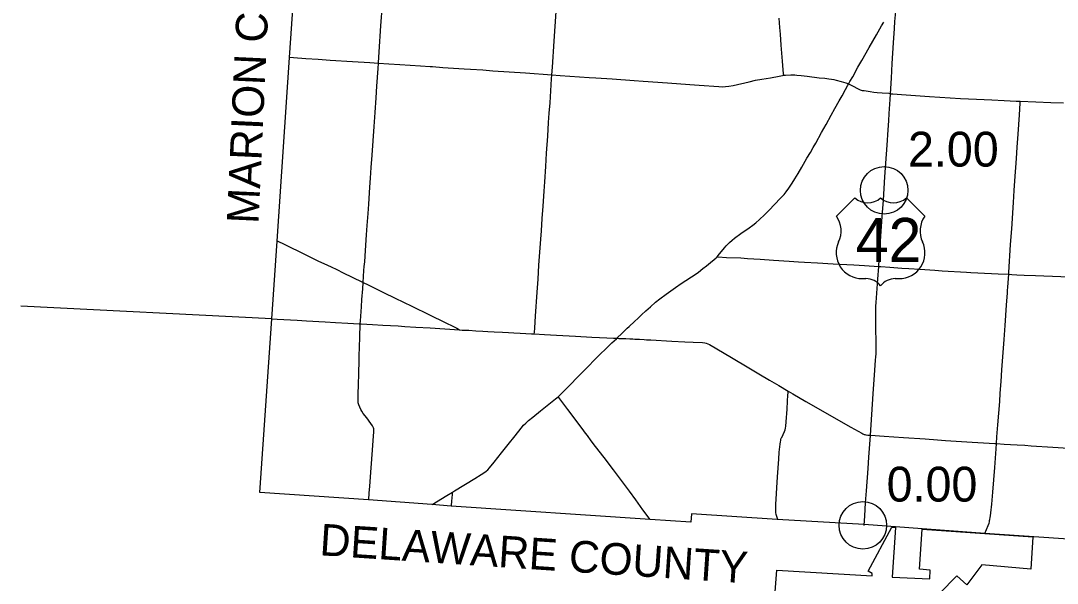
# Model space of a CAD drawing. Extents: x 1815539 to 1947826, y 273303 to 993194.
# Drawn here: x 1815539 to 1848246, y 878565 to 896327 of the extents above; entities that cross this region are included whole.
import ezdxf

# ---------------------------------------------------------------- set-up
doc = ezdxf.new("R2010")
doc.units = 0
for name, color, linetype in [('Default', 7, 'Continuous'), ('GM_X_Adjacent_County_Text', 7, 'Continuous'), ('GM_X_Corporation', 7, 'Continuous'), ('GM_X_County', 7, 'Continuous'), ('GM_X_County_Road', 7, 'Continuous'), ('GM_X_State_Route', 7, 'Continuous'), ('GM_X_Township_Road', 7, 'Continuous'), ('GM_X_US_Route', 7, 'Continuous'), ('PV_X_EOP', 7, 'Continuous'), ('PV_X_Shoulder', 7, 'Continuous')]:
    doc.layers.add(name, color=color, linetype=linetype)

msp = doc.modelspace()

# ---------------------------------------------------------------- linework, layer by layer
at = {"layer": 'Default'}
for centre in [(1842785, 890971), (1842112, 880395)]:
    msp.add_circle(centre, 750, dxfattribs=at)
at = {"layer": 'GM_X_Corporation'}
msp.add_lwpolyline([(1839212, 876522), (1839395, 878979), (1842403, 878797), (1842406, 878874), (1842276, 878944), (1843026, 880333), (1843137, 880326), (1843037, 878758), (1844222, 878701), (1844237, 878976), (1843894, 879006), (1843983, 880269), (1847478, 880034), (1847407, 879013), (1845866, 879149), (1845394, 878513), (1845080, 878796), (1844533, 878238)], dxfattribs=at)
at = {"layer": 'GM_X_County'}
msp.add_lwpolyline([(1850147, 879854), (1845959, 880135), (1842150, 880416), (1839410, 880574), (1836708, 880754), (1836682, 880495), (1835395, 880574), (1829123, 881005), (1828513, 881052), (1826517, 881205), (1823082, 881429), (1823458, 886911), (1823627, 889370), (1824025, 895167), (1824431, 901093)], dxfattribs=at)
at = {"layer": 'GM_X_County_Road'}
for points in [[(1826827, 894987), (1826827, 895001), (1826851, 895345), (1826907, 896163), (1826952, 896835), (1826990, 897375), (1827034, 898063), (1827056, 898390), (1827082, 898783), (1827090, 898914), (1827110, 899258), (1827135, 899684), (1827164, 900142), (1827200, 900716), (1827209, 900922)], [(1841658, 894328), (1841703, 894404), (1841790, 894557), (1841958, 894857), (1842079, 895071), (1842313, 895484), (1842540, 895881), (1842701, 896166), (1842771, 896286)], [(1824029, 895174), (1824145, 895166), (1824536, 895137), (1824929, 895108), (1825305, 895085), (1826010, 895043), (1826550, 895005), (1826827, 894987)], [(1826343, 888063), (1826370, 888438), (1826380, 888568), (1826392, 888715), (1826419, 889075), (1826454, 889567), (1826474, 889861), (1826500, 890238), (1826520, 890532), (1826554, 891073), (1826572, 891351), (1826597, 891695), (1826625, 892087), (1826688, 892988), (1826719, 893430), (1826751, 893888), (1826777, 894264), (1826817, 894821), (1826827, 894987)], [(1826827, 894987), (1827156, 894965), (1827506, 894942)], [(1827506, 894942), (1828155, 894900), (1828455, 894881)], [(1828455, 894881), (1828532, 894877), (1828859, 894855), (1829530, 894810), (1829727, 894798), (1830120, 894771), (1830431, 894749), (1831462, 894677), (1832301, 894618)], [(1832301, 894618), (1832559, 894602), (1833475, 894538), (1833688, 894522), (1834196, 894488), (1834899, 894439), (1835177, 894417), (1835947, 894363), (1836650, 894312), (1836945, 894290), (1837567, 894246), (1837698, 894242), (1837781, 894246), (1837879, 894258), (1838024, 894284), (1838520, 894400), (1838728, 894446), (1838921, 894481), (1839196, 894528), (1839471, 894575), (1839625, 894604), (1839631, 894605)], [(1837518, 888876), (1837551, 888917), (1837744, 889159), (1837799, 889220), (1837903, 889325), (1837988, 889402), (1838065, 889464), (1838264, 889608), (1838521, 889784), (1838642, 889869), (1838731, 889941), (1838854, 890049), (1839010, 890195), (1839158, 890347), (1839507, 890717), (1839630, 890845), (1839695, 890924), (1839778, 891045), (1839879, 891194), (1839966, 891333), (1840066, 891502), (1840183, 891699), (1840348, 891983), (1840455, 892167), (1840546, 892323), (1840627, 892465), (1840809, 892795), (1840954, 893053), (1841113, 893340), (1841232, 893555), (1841367, 893799), (1841454, 893956), (1841565, 894157), (1841635, 894287), (1841658, 894328)], [(1842980, 894022), (1843052, 894018), (1843328, 893998), (1843917, 893956), (1844212, 893937), (1845194, 893876), (1845702, 893848), (1846177, 893824), (1846571, 893808), (1846948, 893791), (1847079, 893786)], [(1847079, 893786), (1847571, 893768), (1848046, 893749), (1848439, 893732)], [(1834737, 886671), (1834904, 886828), (1835023, 886940), (1835130, 887042), (1835261, 887166), (1835407, 887298), (1835568, 887438), (1835710, 887550), (1835908, 887695), (1836201, 887906), (1836376, 888028), (1836527, 888127), (1836707, 888242), (1836815, 888315), (1836921, 888392), (1837065, 888501), (1837181, 888592), (1837309, 888694), (1837421, 888783), (1837481, 888840), (1837518, 888876)], [(1837518, 888876), (1837545, 888874), (1837806, 888855), (1838261, 888836), (1838474, 888821), (1838867, 888795), (1839292, 888768), (1839784, 888737), (1840078, 888719), (1840275, 888709), (1840684, 888683), (1841175, 888655), (1841388, 888641), (1841830, 888620), (1842158, 888602), (1842612, 888567)], [(1842612, 888567), (1842682, 888562), (1842959, 888542), (1843342, 888515), (1843566, 888500), (1843907, 888478), (1844381, 888448), (1844612, 888434), (1845383, 888391), (1845514, 888381), (1845742, 888370), (1846382, 888335), (1846715, 888320)], [(1846715, 888320), (1846809, 888316), (1846970, 888307), (1847201, 888298), (1847560, 888281), (1848363, 888247), (1848986, 888220), (1849660, 888189), (1849954, 888172), (1850381, 888154), (1850806, 888125), (1851229, 888095), (1851932, 888042), (1852343, 888014), (1853211, 887951), (1853436, 887929), (1853686, 887911), (1853918, 887892)], [(1826250, 886755), (1826256, 886850), (1826289, 887292), (1826303, 887521), (1826329, 887865), (1826343, 888063)], [(1826518, 881195), (1826536, 881422), (1826551, 881618), (1826574, 881929), (1826628, 882632), (1826662, 883058), (1826675, 883221), (1826686, 883334), (1826684, 883399), (1826678, 883441), (1826667, 883473), (1826659, 883494), (1826636, 883539), (1826590, 883612), (1826459, 883789), (1826348, 883931), (1826301, 883997), (1826268, 884054), (1826235, 884128), (1826207, 884204), (1826190, 884267), (1826183, 884314), (1826182, 884379), (1826191, 884592), (1826198, 884788), (1826200, 884821), (1826199, 884853), (1826200, 884902), (1826206, 885116), (1826212, 885312), (1826215, 885476), (1826221, 885735), (1826237, 886326), (1826250, 886755)], [(1826250, 886755), (1826282, 886753), (1826642, 886732), (1826970, 886714), (1827445, 886689), (1827658, 886677), (1828002, 886656), (1828461, 886630), (1829384, 886569)], [(1834353, 886304), (1834513, 886458), (1834678, 886615), (1834737, 886671)], [(1829384, 886569), (1829466, 886561), (1829676, 886552), (1829903, 886537), (1830116, 886527), (1830278, 886518), (1830475, 886508), (1830736, 886493), (1830931, 886483), (1831099, 886472), (1831295, 886460), (1831656, 886441), (1831744, 886436)], [(1831744, 886436), (1832062, 886419), (1832440, 886396), (1833047, 886365), (1833562, 886340), (1833797, 886327), (1834032, 886316), (1834242, 886307), (1834353, 886304)], [(1832502, 884457), (1832576, 884525), (1832678, 884631), (1832906, 884865), (1833078, 885042), (1833250, 885217), (1833397, 885371), (1833685, 885663), (1833837, 885813), (1833991, 885960), (1834109, 886073), (1834193, 886152), (1834335, 886287), (1834353, 886304)], [(1834353, 886304), (1834383, 886301), (1834407, 886298), (1834438, 886296), (1834628, 886291), (1834761, 886284), (1834849, 886280), (1834921, 886275)], [(1834921, 886275), (1834961, 886273), (1835065, 886268), (1835206, 886261), (1835289, 886256), (1835418, 886248), (1836089, 886214), (1836498, 886192), (1836760, 886178), (1837055, 886163), (1837120, 886156), (1837169, 886145), (1837216, 886130), (1837276, 886101), (1837967, 885691), (1838515, 885365), (1838829, 885180), (1839168, 884983), (1839465, 884807), (1839753, 884634)], [(1829163, 881447), (1829223, 881484), (1829868, 881877), (1830063, 881997), (1830187, 882077), (1830227, 882105), (1830275, 882149), (1830330, 882209), (1830475, 882386), (1830710, 882682), (1830923, 882952), (1831137, 883222), (1831331, 883466), (1831406, 883553), (1831475, 883623), (1831560, 883701), (1831700, 883815), (1831942, 884008), (1832417, 884385), (1832502, 884457)], [(1839429, 880574), (1839381, 880732), (1839365, 880796), (1839361, 880827), (1839361, 880876), (1839370, 881056), (1839423, 881923), (1839457, 882480), (1839475, 882709), (1839502, 882953), (1839513, 883035), (1839518, 883070), (1839526, 883110), (1839539, 883145), (1839552, 883173), (1839636, 883353), (1839660, 883414), (1839673, 883462), (1839684, 883527), (1839693, 883658), (1839721, 884067), (1839736, 884312), (1839746, 884506), (1839751, 884583), (1839753, 884634)], [(1839753, 884634), (1839900, 884546), (1840313, 884307), (1841735, 883496), (1842075, 883304), (1842113, 883283), (1842148, 883267), (1842176, 883258), (1842206, 883252), (1842265, 883243), (1842304, 883240), (1842349, 883237)], [(1828526, 881056), (1828986, 881338), (1829163, 881447)]]:
    msp.add_lwpolyline(points, dxfattribs=at)
at = {"layer": 'GM_X_State_Route'}
for points in [[(1839619, 894616), (1839616, 894620), (1839611, 894630), (1839608, 894643), (1839606, 894660), (1839600, 894774), (1839578, 895052), (1839536, 895559), (1839509, 895902), (1839492, 896115), (1839481, 896262), (1839474, 896409)], [(1842980, 894022), (1842935, 894024), (1842722, 894040), (1842558, 894052), (1842460, 894062), (1842346, 894078), (1842152, 894108), (1842103, 894117), (1842071, 894126), (1842040, 894137), (1841995, 894156), (1841936, 894185), (1841834, 894240), (1841734, 894295), (1841690, 894316), (1841658, 894328), (1841644, 894334), (1841582, 894353), (1841440, 894394), (1841282, 894437), (1841203, 894456), (1841122, 894471), (1841042, 894483), (1840911, 894498), (1840732, 894516), (1840357, 894561), (1840162, 894586), (1840032, 894601), (1839967, 894607), (1839902, 894609), (1839836, 894607), (1839672, 894597), (1839660, 894597), (1839648, 894599), (1839638, 894601), (1839631, 894605), (1839623, 894611), (1839619, 894616)]]:
    msp.add_lwpolyline(points, dxfattribs=at)
at = {"layer": 'GM_X_Township_Road'}
for points in [[(1832301, 894618), (1832315, 894864), (1832371, 895683), (1832431, 896616), (1832465, 897124), (1832485, 897452), (1832513, 897861), (1832526, 898058), (1832553, 898418), (1832564, 898631), (1832599, 899155), (1832618, 899433), (1832657, 900006), (1832692, 900530), (1832693, 900555)], [(1831744, 886436), (1831748, 886478), (1831759, 886627), (1831784, 887003), (1831835, 887757), (1831862, 888166), (1831892, 888608), (1831910, 888887), (1831949, 889427), (1831968, 889689), (1831995, 890082), (1832023, 890475), (1832054, 890950), (1832073, 891245), (1832105, 891719), (1832134, 892145), (1832168, 892686), (1832197, 893112), (1832217, 893406), (1832240, 893734), (1832292, 894487), (1832301, 894618)], [(1846715, 888320), (1846719, 888377), (1846774, 889261), (1846809, 889752), (1846864, 890587), (1846889, 890964), (1846909, 891275), (1846957, 891978), (1846981, 892339), (1847009, 892747), (1847050, 893353), (1847075, 893729), (1847076, 893746), (1847079, 893786)], [(1823631, 889378), (1823874, 889262), (1824493, 888961), (1824919, 888751), (1825215, 888610), (1825334, 888554), (1825510, 888467), (1825715, 888364), (1825995, 888229), (1826321, 888074), (1826343, 888063)], [(1846329, 882975), (1846343, 883190), (1846371, 883566), (1846430, 884302), (1846449, 884564), (1846476, 884940), (1846501, 885300), (1846568, 886266), (1846600, 886708), (1846648, 887346), (1846669, 887608), (1846674, 887722), (1846675, 887804), (1846683, 887919), (1846715, 888320)], [(1826343, 888063), (1826497, 887987), (1826984, 887750), (1827352, 887571), (1827617, 887441), (1827883, 887313), (1828442, 887038), (1828929, 886803), (1829195, 886675), (1829297, 886620), (1829348, 886591), (1829384, 886569)], [(1823461, 886911), (1823636, 886903), (1824259, 886869), (1824553, 886854), (1825143, 886819), (1825471, 886801), (1825864, 886779), (1826223, 886756), (1826250, 886755)], [(1835397, 880584), (1835168, 880888), (1834946, 881196), (1834743, 881474), (1834374, 881976), (1834246, 882147), (1833946, 882537), (1833673, 882885), (1833534, 883068), (1833418, 883227), (1833361, 883306), (1833304, 883382), (1833187, 883540), (1832805, 884053), (1832550, 884394), (1832520, 884433), (1832502, 884457)], [(1842349, 883237), (1842789, 883208), (1843395, 883168), (1844082, 883122), (1844204, 883114)], [(1844204, 883114), (1844344, 883104), (1844720, 883075), (1845556, 883020), (1846275, 882977), (1846329, 882975)], [(1845958, 880137), (1846066, 880387), (1846093, 880464), (1846103, 880504), (1846112, 880543), (1846119, 880583), (1846128, 880640), (1846134, 880690), (1846146, 880786), (1846176, 881064), (1846212, 881439), (1846274, 882224), (1846297, 882519), (1846317, 882813), (1846329, 882975)], [(1846329, 882975), (1846570, 882962), (1846766, 882949), (1846979, 882935), (1847225, 882921), (1847421, 882907), (1848109, 882864), (1848927, 882815), (1849451, 882781), (1850188, 882733), (1850370, 882722)], [(1829130, 881016), (1829144, 881161), (1829159, 881370), (1829162, 881418), (1829163, 881447)]]:
    msp.add_lwpolyline(points, dxfattribs=at)
at = {"layer": 'GM_X_US_Route'}
for points in [[(1842980, 894022), (1843011, 894513), (1843037, 894972), (1843078, 895627), (1843108, 896085), (1843124, 896298), (1843150, 896623)], [(1842151, 880391), (1842172, 880696), (1842200, 881105), (1842227, 881482), (1842277, 882185), (1842301, 882545), (1842348, 883233), (1842349, 883237), (1842441, 884542), (1842492, 885295), (1842514, 885609), (1842522, 885716), (1842527, 885812), (1842532, 885983), (1842533, 886180), (1842526, 886623), (1842519, 887000), (1842518, 887115), (1842521, 887230), (1842524, 887314), (1842530, 887426), (1842583, 888162), (1842612, 888567), (1842628, 888784), (1842647, 889054), (1842679, 889521), (1842723, 890143), (1842759, 890666), (1842810, 891403), (1842879, 892401), (1842909, 892877), (1842927, 893161), (1842942, 893400), (1842968, 893842), (1842980, 894022)]]:
    msp.add_lwpolyline(points, dxfattribs=at)
at = {"layer": 'PV_X_EOP'}
msp.add_line((1823458, 886911), (1815539, 887318), dxfattribs=at)
at = {"layer": 'PV_X_Shoulder'}
for p, q in [((1841860, 890739), (1841280, 890159)), ((1844064, 890159), (1843484, 890739)), ((1842092, 888186), (1842208, 888186)), ((1843136, 888186), (1843252, 888186))]:
    msp.add_line(p, q, dxfattribs=at)
for centre, radius, start, end in [((1842266, 891153), 580, 225.573, 314.427), ((1843078, 891153), 580, 225.573, 314.427), ((1840614, 889693), 812, 334.5471, 35.0009), ((1844729, 889693), 812, 144.9991, 205.4529), ((1842083, 888998), 812, 154.8319, 270.6383), ((1843261, 888998), 812, 269.3617, 25.1681), ((1842208, 887606), 580, 36.8699, 90), ((1843136, 887606), 580, 90, 143.1301)]:
    msp.add_arc(centre, radius, start, end, dxfattribs=at)

# ---------------------------------------------------------------- texts
at = {"layer": 'Default'}
for s, p in [('2.00', (1843535, 891721)), ('0.00', (1842862, 881145))]:
    msp.add_text(s, height=1100, dxfattribs=at).set_placement(p)
at = {"layer": 'GM_X_Adjacent_County_Text'}
for s, rotation, p in [('MARION COUNTY', 87.3751, (1823040, 889902)), ('DELAWARE COUNTY', 356.2231, (1824953, 879452))]:
    msp.add_text(s, height=1000, rotation=rotation, dxfattribs=at).set_placement(p)
at = {"layer": 'PV_X_Shoulder'}
msp.add_text('42', height=1392.2, dxfattribs=at).set_placement((1841888, 888708))

doc.saveas('drawing.dxf')
